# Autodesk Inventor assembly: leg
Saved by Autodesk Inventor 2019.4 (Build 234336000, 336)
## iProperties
Created: 2020-09
Part Number: leg
Document SubType Name: Assembly
Designer: Administrator
Title: leg
Author: Administrator
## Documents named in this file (5)
- c:\worker\convert-fusion-r07\tmp\job-1\164\output\files\c50c4620-2026-4653-9277-f8972be5ac5a\leg.iam
- c:\worker\convert-fusion-r07\tmp\job-1\164\output\files\c50c4620-2026-4653-9277-f8972be5ac5a\legA.ipt
- c:\worker\convert-fusion-r07\tmp\job-1\164\output\files\c50c4620-2026-4653-9277-f8972be5ac5a\legB.ipt
- c:\worker\convert-fusion-r07\tmp\job-1\164\output\files\c50c4620-2026-4653-9277-f8972be5ac5a\legC.ipt
- c:\worker\convert-fusion-r07\tmp\job-1\164\output\files\c50c4620-2026-4653-9277-f8972be5ac5a\legD.ipt
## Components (4 placed, 4 different names)
1. legA:1
2. legB:1
3. legC:1
4. legD:1
